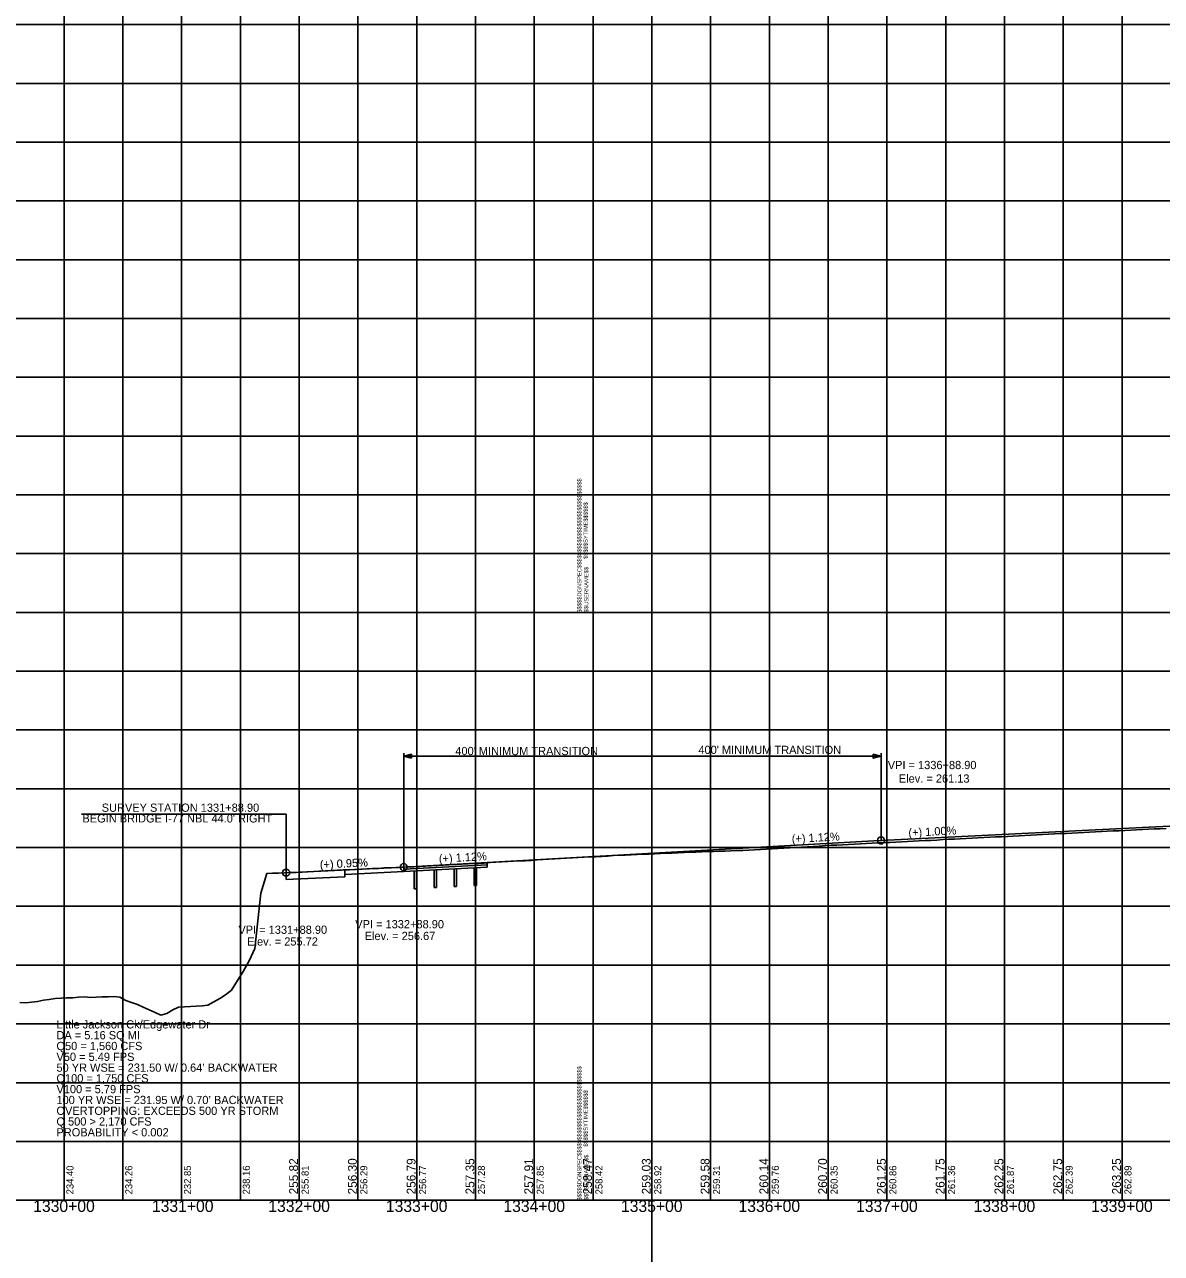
# Model space of a CAD drawing. Extents: x -90830 to 2015517, y -20856 to 836331.
# Drawn here: x 21890 to 22857, y -19432 to -18387 of the extents above; entities that cross this region are included whole.
import ezdxf

# ---------------------------------------------------------------- set-up
doc = ezdxf.new("R2010")
doc.units = 0
for name, color, linetype in [('Level 1', 7, 'Continuous'), ('RD_DDB_GradeTX', 7, 'Continuous'), ('RD_DDB_Profile_Elev', 7, 'Continuous'), ('RD_DDB_Profile_EX', 7, 'Continuous'), ('RD_DDB_Profile_Lbl', 7, 'Continuous'), ('RD_DDB_Profile_PR', 7, 'Continuous'), ('RD_DDB_StaTX', 7, 'Continuous'), ('RD_DDB_StripGrade', 7, 'Continuous'), ('RD_DDB_VCLbl', 7, 'Continuous'), ('RD_GPK_Profile_Cell', 7, 'Continuous'), ('RD_PD_Final_TX', 7, 'Continuous')]:
    doc.layers.add(name, color=color, linetype=linetype)

msp = doc.modelspace()

# ---------------------------------------------------------------- linework, layer by layer
at = {"layer": 'Level 1'}
for p, q in [((22423.5, -12693.4), (22423.5, -20856.1)), ((21923.5, -17886.5), (21923.5, -18386.5)), ((21973.5, -17886.5), (21973.5, -18386.5)), ((22023.5, -17886.5), (22023.5, -18386.5)), ((22073.5, -17886.5), (22073.5, -18386.5)), ((22123.5, -17886.5), (22123.5, -18386.5)), ((22173.5, -17886.5), (22173.5, -18386.5)), ((22223.5, -17886.5), (22223.5, -18386.5)), ((22273.5, -17886.5), (22273.5, -18386.5)), ((22323.5, -17886.5), (22323.5, -18386.5)), ((22373.5, -17886.5), (22373.5, -18386.5)), ((22373.5, -17886.5), (22373.5, -18386.5)), ((22373.5, -17886.5), (22373.5, -18386.5)), ((22423.5, -17886.5), (22423.5, -18386.5)), ((22473.5, -17886.5), (22473.5, -18386.5)), ((22523.5, -17886.5), (22523.5, -18386.5)), ((22573.5, -17886.5), (22573.5, -18386.5)), ((22623.5, -17886.5), (22623.5, -18386.5)), ((22673.5, -17886.5), (22673.5, -18386.5)), ((22723.5, -17886.5), (22723.5, -18386.5)), ((22773.5, -17886.5), (22773.5, -18386.5)), ((22823.5, -17886.5), (22823.5, -18386.5)), ((20773.5, -18386.5), (22373.5, -18386.5)), ((20773.5, -18386.5), (22373.5, -18386.5)), ((21923.5, -18386.5), (21923.5, -18886.5)), ((21973.5, -18386.5), (21973.5, -18886.5)), ((22023.5, -18386.5), (22023.5, -18886.5)), ((22073.5, -18386.5), (22073.5, -18886.5)), ((22123.5, -18386.5), (22123.5, -18886.5)), ((22173.5, -18386.5), (22173.5, -18886.5)), ((22223.5, -18386.5), (22223.5, -18886.5)), ((22273.5, -18386.5), (22273.5, -18886.5)), ((22323.5, -18386.5), (22323.5, -18886.5)), ((22373.5, -18386.5), (22373.5, -18886.5)), ((22373.5, -18386.5), (22373.5, -18886.5)), ((22373.5, -18386.5), (23973.5, -18386.5)), ((22373.5, -18386.5), (22373.5, -18886.5)), ((22373.5, -18386.5), (23973.5, -18386.5)), ((22423.5, -18386.5), (22423.5, -18886.5)), ((22473.5, -18386.5), (22473.5, -18886.5)), ((22523.5, -18386.5), (22523.5, -18886.5)), ((22573.5, -18386.5), (22573.5, -18886.5)), ((22623.5, -18386.5), (22623.5, -18886.5)), ((22673.5, -18386.5), (22673.5, -18886.5)), ((22723.5, -18386.5), (22723.5, -18886.5)), ((22773.5, -18386.5), (22773.5, -18886.5)), ((22823.5, -18386.5), (22823.5, -18886.5)), ((20773.5, -18436.5), (22373.5, -18436.5)), ((22373.5, -18436.5), (23973.5, -18436.5)), ((20773.5, -18486.5), (22373.5, -18486.5)), ((22373.5, -18486.5), (23973.5, -18486.5)), ((20773.5, -18536.5), (22373.5, -18536.5)), ((22373.5, -18536.5), (23973.5, -18536.5)), ((20773.5, -18586.5), (22373.5, -18586.5)), ((22373.5, -18586.5), (23973.5, -18586.5)), ((20773.5, -18636.5), (22373.5, -18636.5)), ((22373.5, -18636.5), (23973.5, -18636.5)), ((20773.5, -18686.5), (22373.5, -18686.5)), ((22373.5, -18686.5), (23973.5, -18686.5)), ((20773.5, -18736.5), (22373.5, -18736.5)), ((22373.5, -18736.5), (23973.5, -18736.5)), ((20773.5, -18786.5), (22373.5, -18786.5)), ((22373.5, -18786.5), (23973.5, -18786.5)), ((20773.5, -18836.5), (22373.5, -18836.5)), ((22373.5, -18836.5), (23973.5, -18836.5)), ((20773.5, -18886.5), (22373.5, -18886.5)), ((20773.5, -18886.5), (22373.5, -18886.5)), ((21923.5, -18886.5), (21923.5, -19386.5)), ((21973.5, -18886.5), (21973.5, -19386.5)), ((22023.5, -18886.5), (22023.5, -19386.5)), ((22073.5, -18886.5), (22073.5, -19386.5)), ((22123.5, -18886.5), (22123.5, -19386.5)), ((22173.5, -18886.5), (22173.5, -19386.5)), ((22223.5, -18886.5), (22223.5, -19386.5)), ((22273.5, -18886.5), (22273.5, -19386.5)), ((22323.5, -18886.5), (22323.5, -19386.5)), ((22373.5, -18886.5), (23973.5, -18886.5)), ((22373.5, -18886.5), (22373.5, -19386.5)), ((22373.5, -18886.5), (22373.5, -19386.5)), ((22373.5, -18886.5), (23973.5, -18886.5)), ((22373.5, -18886.5), (22373.5, -19386.5)), ((22423.5, -18886.5), (22423.5, -19386.5)), ((22473.5, -18886.5), (22473.5, -19386.5)), ((22523.5, -18886.5), (22523.5, -19386.5)), ((22573.5, -18886.5), (22573.5, -19386.5)), ((22623.5, -18886.5), (22623.5, -19386.5)), ((22673.5, -18886.5), (22673.5, -19386.5)), ((22723.5, -18886.5), (22723.5, -19386.5)), ((22773.5, -18886.5), (22773.5, -19386.5)), ((22823.5, -18886.5), (22823.5, -19386.5)), ((20773.5, -18936.5), (22373.5, -18936.5)), ((22373.5, -18936.5), (23973.5, -18936.5)), ((20773.5, -18986.5), (22373.5, -18986.5)), ((22373.5, -18986.5), (23973.5, -18986.5)), ((20773.5, -19036.5), (22373.5, -19036.5)), ((22373.5, -19036.5), (23973.5, -19036.5)), ((20773.5, -19086.5), (22373.5, -19086.5)), ((22373.5, -19086.5), (23973.5, -19086.5)), ((20773.5, -19136.5), (22373.5, -19136.5)), ((22373.5, -19136.5), (23973.5, -19136.5)), ((20773.5, -19186.5), (22373.5, -19186.5)), ((22373.5, -19186.5), (23973.5, -19186.5)), ((20773.5, -19236.5), (22373.5, -19236.5)), ((22373.5, -19236.5), (23973.5, -19236.5)), ((20773.5, -19286.5), (22373.5, -19286.5)), ((22373.5, -19286.5), (23973.5, -19286.5)), ((20773.5, -19336.5), (22373.5, -19336.5)), ((22373.5, -19336.5), (23973.5, -19336.5)), ((20773.5, -19386.5), (22373.5, -19386.5)), ((22373.5, -19386.5), (23973.5, -19386.5))]:
    msp.add_line(p, q, dxfattribs=at)
at = {"layer": 'RD_DDB_GradeTX'}
for centre in [(22618.5, -19080.5), (22112.4, -19107.9), (22212.4, -19103.2)]:
    msp.add_circle(centre, 3, dxfattribs=at)
at = {"layer": 'RD_DDB_Profile_EX'}
for points in [[(22545.9, -19086.4), (22550.9, -19086.1), (22555.9, -19085.8), (22560.9, -19085.5), (22565.9, -19085.2), (22570.9, -19084.9), (22575.9, -19084.6), (22580.9, -19084.4), (22585.9, -19084.1), (22590.9, -19083.8), (22595.9, -19083.6), (22600.9, -19083.3), (22605.9, -19083.1), (22610.9, -19082.8), (22615.9, -19082.6), (22620.9, -19082.3), (22625.9, -19082.1), (22630.9, -19081.8), (22635.9, -19081.6), (22640.9, -19081.3), (22645.9, -19081.1), (22650.9, -19080.9), (22655.9, -19080.6), (22660.9, -19080.4), (22665.9, -19080.1), (22670.9, -19079.8), (22675.9, -19079.5), (22680.9, -19079.3), (22685.9, -19079), (22690.9, -19078.8), (22695.9, -19078.5), (22700.9, -19078.3), (22705.9, -19078), (22710.9, -19077.8), (22715.9, -19077.5), (22720.9, -19077.3), (22725.9, -19077), (22730.9, -19076.7), (22735.9, -19076.5), (22740.9, -19076.2), (22745.9, -19075.9), (22750.9, -19075.7), (22755.9, -19075.4), (22760.9, -19075.2), (22765.9, -19074.9), (22770.9, -19074.7), (22775.9, -19074.5), (22780.9, -19074.2), (22785.9, -19073.9), (22790.9, -19073.7), (22795.9, -19073.4), (22800.9, -19073.1), (22805.9, -19072.9), (22810.9, -19072.7), (22815.9, -19072.4), (22820.9, -19072.2), (22825.9, -19071.9), (22830.9, -19071.7), (22835.9, -19071.5), (22840.9, -19071.2), (22845.9, -19071), (22850.9, -19070.7), (22855.9, -19070.5), (22860.9, -19070.2)], [(22045.9, -19220.6), (22050.9, -19217.7), (22055.9, -19214.8), (22060.9, -19211.8), (22065.9, -19207.7), (22070.9, -19199.7), (22075.9, -19191.8), (22080.9, -19182.8), (22085.9, -19172.3), (22090.9, -19125.2), (22095.9, -19108.7), (22100.9, -19108.4), (22105.9, -19108.2), (22110.9, -19108), (22115.9, -19107.8), (22120.9, -19107.6), (22125.9, -19107.4), (22130.9, -19107.1), (22135.9, -19106.9), (22140.9, -19106.6), (22145.9, -19106.3), (22150.9, -19106.1), (22155.9, -19105.8), (22160.9, -19105.6), (22165.9, -19105.4), (22170.9, -19105.2), (22175.9, -19104.9), (22180.9, -19104.7), (22185.9, -19104.4), (22190.9, -19104.2), (22195.9, -19103.9), (22200.9, -19103.7), (22205.9, -19103.5), (22210.9, -19103.2), (22215.9, -19103), (22220.9, -19102.8), (22225.9, -19102.6), (22230.9, -19102.4), (22235.9, -19102.1), (22240.9, -19101.8), (22245.9, -19101.5), (22250.9, -19101.2), (22255.9, -19101), (22260.9, -19100.7), (22265.9, -19100.5), (22270.9, -19100.2), (22275.9, -19100), (22280.9, -19099.7), (22285.9, -19099.3), (22290.9, -19099), (22295.9, -19098.7), (22300.9, -19098.5), (22305.9, -19098.2), (22310.9, -19097.9), (22315.9, -19097.7), (22320.9, -19097.4), (22325.9, -19097.1), (22330.9, -19096.8), (22335.9, -19096.5), (22340.9, -19096.2), (22345.9, -19095.9), (22350.9, -19095.6), (22355.9, -19095.3), (22360.9, -19095.1), (22365.9, -19094.8), (22370.9, -19094.5), (22375.9, -19094.3), (22380.9, -19094), (22385.9, -19093.7), (22390.9, -19093.4), (22395.9, -19093.1), (22400.9, -19092.9), (22405.9, -19092.7), (22410.9, -19092.5), (22415.9, -19092.2), (22420.9, -19092), (22425.9, -19091.8), (22430.9, -19091.6), (22435.9, -19091.4), (22440.9, -19091.2), (22445.9, -19091), (22450.9, -19090.7), (22455.9, -19090.5), (22460.9, -19090.4), (22465.9, -19090.2), (22470.9, -19090), (22475.9, -19089.9), (22480.9, -19089.7), (22485.9, -19089.5), (22490.9, -19089.3), (22495.9, -19089.1), (22500.9, -19088.9), (22505.9, -19088.6), (22510.9, -19088.4), (22515.9, -19088.2), (22520.9, -19087.9), (22525.9, -19087.6), (22530.9, -19087.3), (22535.9, -19087), (22540.9, -19086.7), (22545.9, -19086.4)], [(21885.9, -19218.3), (21890.9, -19218.5), (21895.9, -19217.9), (21900.9, -19217.5), (21905.9, -19216.4), (21910.9, -19215.8), (21915.9, -19215), (21920.9, -19214.6), (21925.9, -19214.4), (21930.9, -19214.2), (21935.9, -19213.9), (21940.9, -19213.4), (21945.9, -19214), (21950.9, -19213.8), (21955.9, -19213.6), (21960.9, -19213.5), (21965.9, -19213.2), (21970.9, -19213.8), (21975.9, -19216.6), (21980.9, -19218.3), (21985.9, -19220.1), (21990.9, -19222.3), (21995.9, -19224.5), (22000.9, -19226.8), (22005.9, -19229), (22010.9, -19227.6), (22015.9, -19224.6), (22020.9, -19222.4), (22025.9, -19222.1), (22030.9, -19221.8), (22035.9, -19221.5), (22040.9, -19221.2), (22045.9, -19220.6)]]:
    msp.add_lwpolyline(points, dxfattribs=at)
at = {"layer": 'RD_DDB_Profile_Lbl'}
for p in [(21938.2, -19058), (22112.4, -19107.9)]:
    msp.add_line(p, (22112.4, -19058), dxfattribs=at)
at = {"layer": 'RD_DDB_Profile_PR'}
msp.add_line((22618.5, -19080.5), (24061, -19008.3), dxfattribs=at)
msp.add_lwpolyline([(22112.4, -19107.9), (22112.4, -19107.9), (22212.4, -19103.2), (22612.4, -19080.8), (22618.5, -19080.5)], dxfattribs=at)
at = {"layer": 'RD_DDB_VCLbl'}
for p, q in [((22212.4, -19103.4), (22212.4, -19006.3)), ((22212.4, -19008.8), (22618.5, -19008.8)), ((22618.5, -19081), (22618.5, -19006.3))]:
    msp.add_line(p, q, dxfattribs=at)
at = {"layer": 'RD_GPK_Profile_Cell'}
msp.add_line((4823.5, -19386.5), (75223.5, -19386.5), dxfattribs=at)
at = {"layer": 'RD_PD_Final_TX'}
for p, q in [((22208.1, -19103.4), (22158.1, -19105.7)), ((22162.4, -19111.3), (22162.4, -19105.5)), ((22212.4, -19103.2), (22283.4, -19099.6)), ((22212.4, -19104.8), (22283.4, -19101.2)), ((22212.4, -19106.9), (22212.4, -19103.2)), ((22212.4, -19106.9), (22283.4, -19103.3)), ((22221.4, -19121.5), (22221.4, -19106.4)), ((22223.4, -19106.3), (22223.4, -19121.5)), ((22238.4, -19120.6), (22238.4, -19105.6)), ((22240.4, -19105.5), (22240.4, -19120.5)), ((22255.4, -19119.7), (22255.4, -19104.7)), ((22257.4, -19104.6), (22257.4, -19119.6)), ((22272.4, -19118.9), (22272.4, -19103.9)), ((22274.4, -19118.9), (22274.4, -19103.8)), ((22283.4, -19099.6), (22283.4, -19103.3)), ((22112.4, -19107.9), (22112.4, -19113.8)), ((22112.4, -19113.8), (22162.4, -19111.3)), ((22212.4, -19106.9), (22162.4, -19109.3)), ((22223.4, -19121.5), (22221.4, -19121.5)), ((22240.4, -19120.6), (22238.4, -19120.6)), ((22257.4, -19119.7), (22255.4, -19119.7)), ((22274.4, -19118.9), (22272.4, -19118.9))]:
    msp.add_line(p, q, dxfattribs=at)
for points in [[(22219, -19010.5), (22212.4, -19008.8), (22219, -19007.2)], [(22611.9, -19007.2), (22618.5, -19008.8), (22611.9, -19010.5)]]:
    msp.add_lwpolyline(points, close=True, dxfattribs=at)

# ---------------------------------------------------------------- texts
at = {"layer": 'Level 1'}
for s, p in [('$$$$$DGNSPEC$$$$$$$$$$$$$$$$$$$$$$$$$$$$', (22363.6, -18886.6)), ('$$$$$SYTIME$$$$$$', (22368.9, -18841)), ('$$USERNAME$$', (22369.5, -18886.4)), ('$$$$$DGNSPEC$$$$$$$$$$$$$$$$$$$$$$$$$$$$', (22363.6, -19386.6)), ('$$$$$SYTIME$$$$$$', (22368.9, -19341)), ('$$USERNAME$$', (22369.5, -19386.4))]:
    msp.add_text(s, height=3.544, rotation=90, dxfattribs=at).set_placement(p)
at = {"layer": 'RD_DDB_GradeTX'}
for s, rotation, p in [('(+) 1.12%', 3.1934, (22542.7, -19082.7)), ('(+) 1.00%', 2.8661, (22641.9, -19077.4)), ('(+) 0.95%', 2.7308, (22141.2, -19104.5)), ('(+) 0.95%', 2.7308, (22141.3, -19104.5)), ('(+) 1.12%', 3.1934, (22242.5, -19099.5))]:
    msp.add_text(s, height=7, rotation=rotation, dxfattribs=at).set_placement(p)
at = {"layer": 'RD_DDB_Profile_Elev'}
for s, p in [('255.82', (22122.5, -19381.5)), ('256.30', (22172.5, -19381.5)), ('256.79', (22222.5, -19381.5)), ('257.35', (22272.5, -19381.5)), ('257.91', (22322.5, -19381.5)), ('258.47', (22372.5, -19381.5)), ('259.03', (22422.5, -19381.5)), ('259.58', (22472.5, -19381.5)), ('260.14', (22522.5, -19381.5)), ('260.70', (22572.5, -19381.5)), ('261.25', (22622.5, -19381.5)), ('261.75', (22672.5, -19381.5)), ('262.25', (22722.5, -19381.5)), ('262.75', (22772.5, -19381.5)), ('263.25', (22822.5, -19381.5))]:
    msp.add_text(s, height=7.5, rotation=90, dxfattribs=at).set_placement(p)
at = {"layer": 'RD_DDB_Profile_Lbl'}
for s, p in [('VPI = 1336+88.90', (22624.2, -19019.8)), ('Elev. = 261.13', (22633.6, -19031.3)), ('SURVEY STATION 1331+88.90', (21955.5, -19056.1)), ("BEGIN BRIDGE I-77 NBL 44.0' RIGHT", (21939.1, -19065.2)), ('VPI = 1332+88.90', (22171.2, -19155.2)), ('VPI = 1331+88.90', (22071.8, -19159.9)), ('Elev. = 256.67', (22179.2, -19165.2)), ('Elev. = 255.72', (22079.3, -19169.9)), ('Little Jackson Ck/Edgewater Dr', (21917, -19240.4)), ('DA = 5.16 SQ MI', (21917, -19249.6)), ('Q50 = 1,560 CFS', (21917, -19258.8)), ('V50 = 5.49 FPS', (21917, -19268)), ('50 YR WSE = 231.50 W/ 0.64’ BACKWATER', (21917, -19277.2)), ('Q100 = 1,750 CFS', (21917, -19286.3)), ('V100 = 5.79 FPS', (21917, -19295.5)), ('100 YR WSE = 231.95 W/ 0.70’ BACKWATER', (21917, -19304.7)), ('OVERTOPPING: EXCEEDS 500 YR STORM', (21917, -19313.9)), ('Q 500 > 2,170 CFS', (21917, -19323)), ('PROBABILITY < 0.002', (21917, -19332.2))]:
    msp.add_text(s, height=7, dxfattribs=at).set_placement(p)
at = {"layer": 'RD_DDB_StaTX'}
for s, p in [('1330+00', (21897.2, -19396.5)), ('1331+00', (21998.2, -19396.5)), ('1332+00', (22097.2, -19396.5)), ('1333+00', (22197.2, -19396.5)), ('1334+00', (22297.2, -19396.5)), ('1335+00', (22397.2, -19396.5)), ('1336+00', (22497.2, -19396.5)), ('1337+00', (22597.2, -19396.5)), ('1338+00', (22697.2, -19396.5)), ('1339+00', (22797.2, -19396.5))]:
    msp.add_text(s, height=10, dxfattribs=at).set_placement(p)
at = {"layer": 'RD_DDB_StripGrade'}
for s, p in [('234.40', (21931.5, -19381.5)), ('234.26', (21981.5, -19381.5)), ('232.85', (22031.5, -19381.5)), ('238.16', (22081.5, -19381.5)), ('255.81', (22131.5, -19381.5)), ('256.29', (22181.5, -19381.5)), ('256.77', (22231.5, -19381.5)), ('257.28', (22281.5, -19381.5)), ('257.85', (22331.5, -19381.5)), ('258.42', (22381.5, -19381.5)), ('258.92', (22431.5, -19381.5)), ('259.31', (22481.5, -19381.5)), ('259.76', (22531.5, -19381.5)), ('260.35', (22581.5, -19381.5)), ('260.86', (22631.5, -19381.5)), ('261.36', (22681.5, -19381.5)), ('261.87', (22731.5, -19381.5)), ('262.39', (22781.5, -19381.5)), ('262.89', (22831.5, -19381.5))]:
    msp.add_text(s, height=6, rotation=90, dxfattribs=at).set_placement(p)
at = {"layer": 'RD_DDB_VCLbl'}
for p in [(22256.3, -19007.9), (22463.1, -19006.9)]:
    msp.add_text("400' MINIMUM TRANSITION", height=7, dxfattribs=at).set_placement(p)

doc.saveas('drawing.dxf')
